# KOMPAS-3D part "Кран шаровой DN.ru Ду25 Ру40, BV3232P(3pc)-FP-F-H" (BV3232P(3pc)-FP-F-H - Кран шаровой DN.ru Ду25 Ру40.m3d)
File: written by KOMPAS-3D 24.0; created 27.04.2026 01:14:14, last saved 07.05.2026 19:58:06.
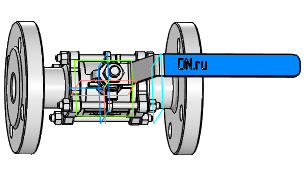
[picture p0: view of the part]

Document properties: Автор: Максим; Полное имя файла: BVxxP(3pc)-FP-F-H - Кран шаровой DN.ru Ду25 Ру40.cdw

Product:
- Body: Тело 1  | qty 1
    Масса: 3.757809
- Part/product: Кран шаровой DN.ru Ду25 Ру40  | designation BV3232P(3pc)-FP-F-H
    Масса: 3.43
    Раздел спецификации: Прочие изделия
    Форматы листов документа: A3
    Примечание: D160-22803

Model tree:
1. Операция без истории:1
2. Эскиз:1  (with: Грань.Операция без истории:1)
3. Элемент выдавливания:1
     Расстояние 1 = 8; Расстояние 2 = 15
4. Эскиз:2  (with: Грань.Элемент выдавливания:1)
5. Элемент выдавливания:2  (with: Грань.Операция без истории:1)
     Расстояние 1 = 15
6. Эскиз:3  (with: Грань.Операция без истории:1)
7. Элемент выдавливания:3
     Расстояние 1 = 5
8. Фаска:1  (with: Ребро.Элемент выдавливания:3)
     Угол = 45; Длина 1 = 1; Длина 2 = 1
9. Эскиз:4  (with: Ребро.Операция без истории:1)
10. Элемент выдавливания:4
     Расстояние 1 = 7
11. Эскиз:5  (with: Ребро.Элемент выдавливания:4)
12. Элемент выдавливания:5
     Расстояние 1 = 19
13. Фаска:2  (with: Ребро.Элемент выдавливания:5)
     Угол = 45; Длина 1 = 5; Длина 2 = 5
14. Эскиз:6  (with: Ребро.Элемент выдавливания:5)
15. Элемент выдавливания:6
     Расстояние 1 = 20
16. Скругление:1  (with: Ребро.Элемент выдавливания:6)
     Радиус = 6.25
17. Скругление:2  (with: Ребро.Элемент выдавливания:4)
     Радиус = 2.5
18. Скругление:3  (with: Ребро.Элемент выдавливания:4)
     Радиус = 5
19. Эскиз:7  (with: Грань.Операция без истории:1, Ребро.Операция без истории:1)
20. Элемент выдавливания:7  (with: Грань.Операция без истории:1)
21. Смещенная плоскость:1
     Расстояние = -47
22. Эскиз:8  (with: Ребро.Операция без истории:1)
23. Элемент выдавливания:8
     Расстояние 1 = 16
24. Зеркальный массив:1
25. Экземпляр ( 1 )
26. Экземпляр ( 2 )  (with: Элемент выдавливания:8)
27. Эскиз:9  (with: Грань.Операция без истории:1)
28. Элемент выдавливания:9
     Расстояние 1 = 10
29. Эскиз:10  (with: Грань.Операция без истории:1)
30. Элемент выдавливания:10
     Расстояние 1 = 0.2
31. Скругление:4  (with: Ребро.Элемент выдавливания:6)
     Радиус = 0.5
32. Эскиз:11  (with: Грань.Операция без истории:1)
33. Элемент выдавливания:11
     Расстояние 1 = 0.2
34. Эскиз:12  (with: Грань.Элемент выдавливания:6, Ребро.Элемент выдавливания:6, Ребро.Скругление:4)
35. Элемент выдавливания:12
     Расстояние 2 = 0.2

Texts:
  BV3232P(3pc)-FP-F-H
  DN25 PN40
